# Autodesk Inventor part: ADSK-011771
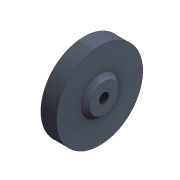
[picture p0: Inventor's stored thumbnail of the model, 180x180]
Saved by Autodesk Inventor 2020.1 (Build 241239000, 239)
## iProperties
Created: 2000-02
Part Number: ADSK-011771
Material: RA Nylatron
Document SubType Name: Modeling
Designer: dmcquary
Density: 1.13867 g/cm^3
Appearance: Nylatron
Mass: 44.642 g
Surface Area: 82.5304 cm^2
Volume: 39.2054 cm^3
Control State: 0
Checked Out: False
Master: False
Shininess: 0.0
Length Units: 11269
Angle Units: 11279
Time Units: 11290
Mass Units: 11283
Length Display Precision: 3
Angle Display Precision: 2
Compacted: True
Dimensions: 19,5x60x60 mm
Mass: 0,045 kg
Density: 0.0
Volumn: 0.0
Area: 0.0
PropertySet Name: Model Information
Author: dmcquary
Revision Number: -
Title: ADSK-011771
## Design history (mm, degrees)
node "Solide1"
  node "Revolution1" dims "d9" = 360 deg
  node "Hole1" dims "d10" = 6.647, "d11" = 9.525, "d12" = 6.35, "d13" = 60 deg, "d14" = 16, "d15" = 118 deg, "d19" = 12
sketch "Sketch1"
  geometry: L1 (-11, 0)-(-11, 30); L2 (-11, 30)-(0, 30); L3 (0, 30)-(0, 0); L4 (3, 0)-(3, 10); L5 (3, 10)-(0, 13); L6 (-16.5, 0)-(3, 0); A1 r 80 centre (63.5, 0) between (-11, 29.15) and (-16.5, 0)
  constraints: 12 end point, 5 point on line, 2 point on circle, 1 centre point, 1 horizontal, 1 parallel, 1 vertical
  dimensions: "d2" = 11 distance of L1.end L2.end; "d3" = 5.5 distance of L1.start L6.start; "d4" = 80 radius of A1; "d6" = 3 distance between parallel lines of L4 L3; "d16" = 60 diameter of L2 L6; "d17" = 20 diameter of L4.end L6; "d18" = 45 deg angle of L5 L4
sketch "Sketch2"
  geometry: C1 r 10 at (0, 0) reference; 1 further point
  constraints: 1 coincident
node "Corps solides"
node "Corps surfaciques"
